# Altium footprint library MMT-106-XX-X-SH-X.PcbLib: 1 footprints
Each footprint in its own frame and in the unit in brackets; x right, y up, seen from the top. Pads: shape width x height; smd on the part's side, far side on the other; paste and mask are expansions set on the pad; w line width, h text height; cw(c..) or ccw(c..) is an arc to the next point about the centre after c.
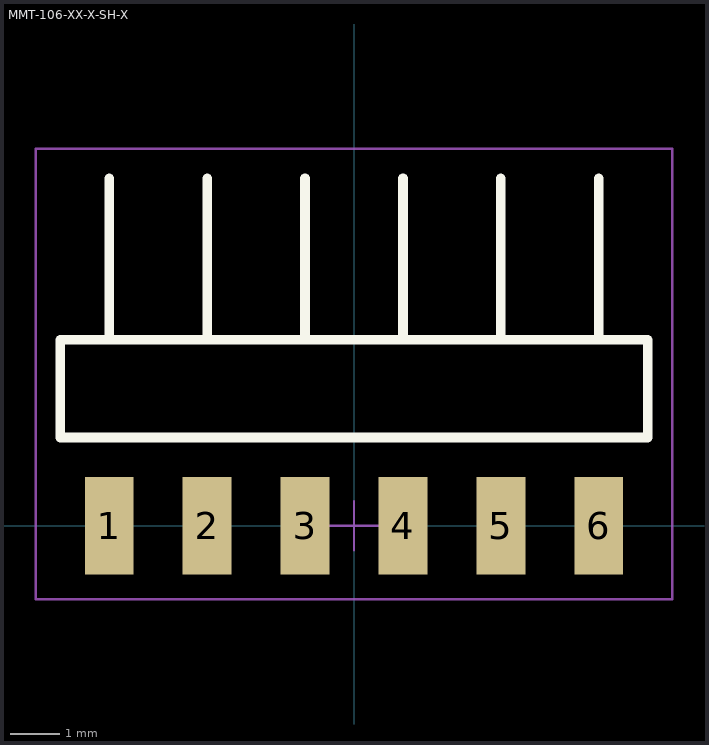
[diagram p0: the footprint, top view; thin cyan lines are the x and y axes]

## MMT-106-XX-X-SH-X [mm] "2.00mm pitch, 6 pin, header; single row"
height 2
pads (6):
  rect 1x2 smd mask+0: 1(-5,0) 2(-3,0) 3(-1,0) 4(1,0) 5(3,0) 6(5,0)
Top Overlay:
  lines w0.2: -5,3.9 -5,7.1 ; -3,3.9 -3,7.1 ; -1,3.9 -1,7.1 ; 1,3.9 1,7.1 ; 3,3.9 3,7.1 ; 5,3.9 5,7.1 ; -6,1.8 6,1.8 6,3.8 -6,3.8 -6,1.8
Mechanical 13:
  lines w0.1: -5,3.9 -5,7.1 ; -3,3.9 -3,7.1 ; -1,3.9 -1,7.1 ; 1,3.9 1,7.1 ; 3,3.9 3,7.1 ; 5,3.9 5,7.1 ; -6,1.8 6,1.8 6,3.8 -6,3.8 -6,1.8
  text ".Designator" at 0.254,0.254 h1.52
Mechanical 15:
  lines w0.05: -0.5,0 0.5,0 ; 0,-0.5 0,0.5 ; -6.5,-1.5 6.5,-1.5 6.5,7.7 -6.5,7.7 -6.5,-1.5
